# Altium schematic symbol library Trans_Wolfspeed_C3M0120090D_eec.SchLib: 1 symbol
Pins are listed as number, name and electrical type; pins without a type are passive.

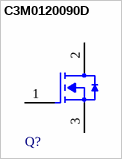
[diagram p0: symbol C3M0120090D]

## C3M0120090D
designator Q?  (value not drawn)
pins: 1 Gate, 2 Drain, 3 Source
